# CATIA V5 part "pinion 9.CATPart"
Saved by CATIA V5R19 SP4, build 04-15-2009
Part number: pinion 9
Bounding box of the stored display mesh (mm): x 0 to 22.15, y -26.556 to 26.556, z -26.362 to 26.362
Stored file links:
  G:\EU_thinkMotion\CFAO_2010\MMS_groupe1\MMS_groupe1\A reprendre\OK\rdeneffle\pinion 9.CATPart
  G:\EU_thinkMotion\CFAO_2010\MMS_groupe1\MMS_groupe1\A reprendre\OK\rdeneffle\pinion 2.CATPart
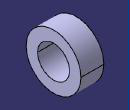
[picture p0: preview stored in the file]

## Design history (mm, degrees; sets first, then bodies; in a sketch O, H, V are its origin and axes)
Parameters
  `rayon interieur.1` = 15.505 mm
  `rayon extérieur.1` = 26.556 mm
Body1 (main body)
Body2
  Sketch1 on yz-plane, origin (0, 0, 0), H (0, 1, 0), V (0, 0, 1)
    circle A1 centre (0, 0) radius 15.505
    circle A2 centre (0, 0) radius 26.556
    radius A2 = 26.556 {= `rayon extérieur.1`}
    radius A1 = 15.505 {= `rayon interieur.1`}
  Pad1: profile Sketch1, direction (1, 0, 0), length 22.15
